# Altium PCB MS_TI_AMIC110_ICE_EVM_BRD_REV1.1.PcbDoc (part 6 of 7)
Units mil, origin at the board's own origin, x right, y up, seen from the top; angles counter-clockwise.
Board outline 3464.57 x 2204.72 mil, 8 copper layers (TopLayer - S1 (.GTL), MidLayer1 - S2 (.G1), MidLayer2 - S3 (.G2), MidLayer3 - S4 (.G3), MidLayer4 - S5 (.G4), MidLayer5 - S6 (.G5), MidLayer6 - S7 (.G6), BottomLayer - S8 (.GBL)), stack 58.937 mil thick; 504 components, 369 nets, 1811 pads, 874 vias.
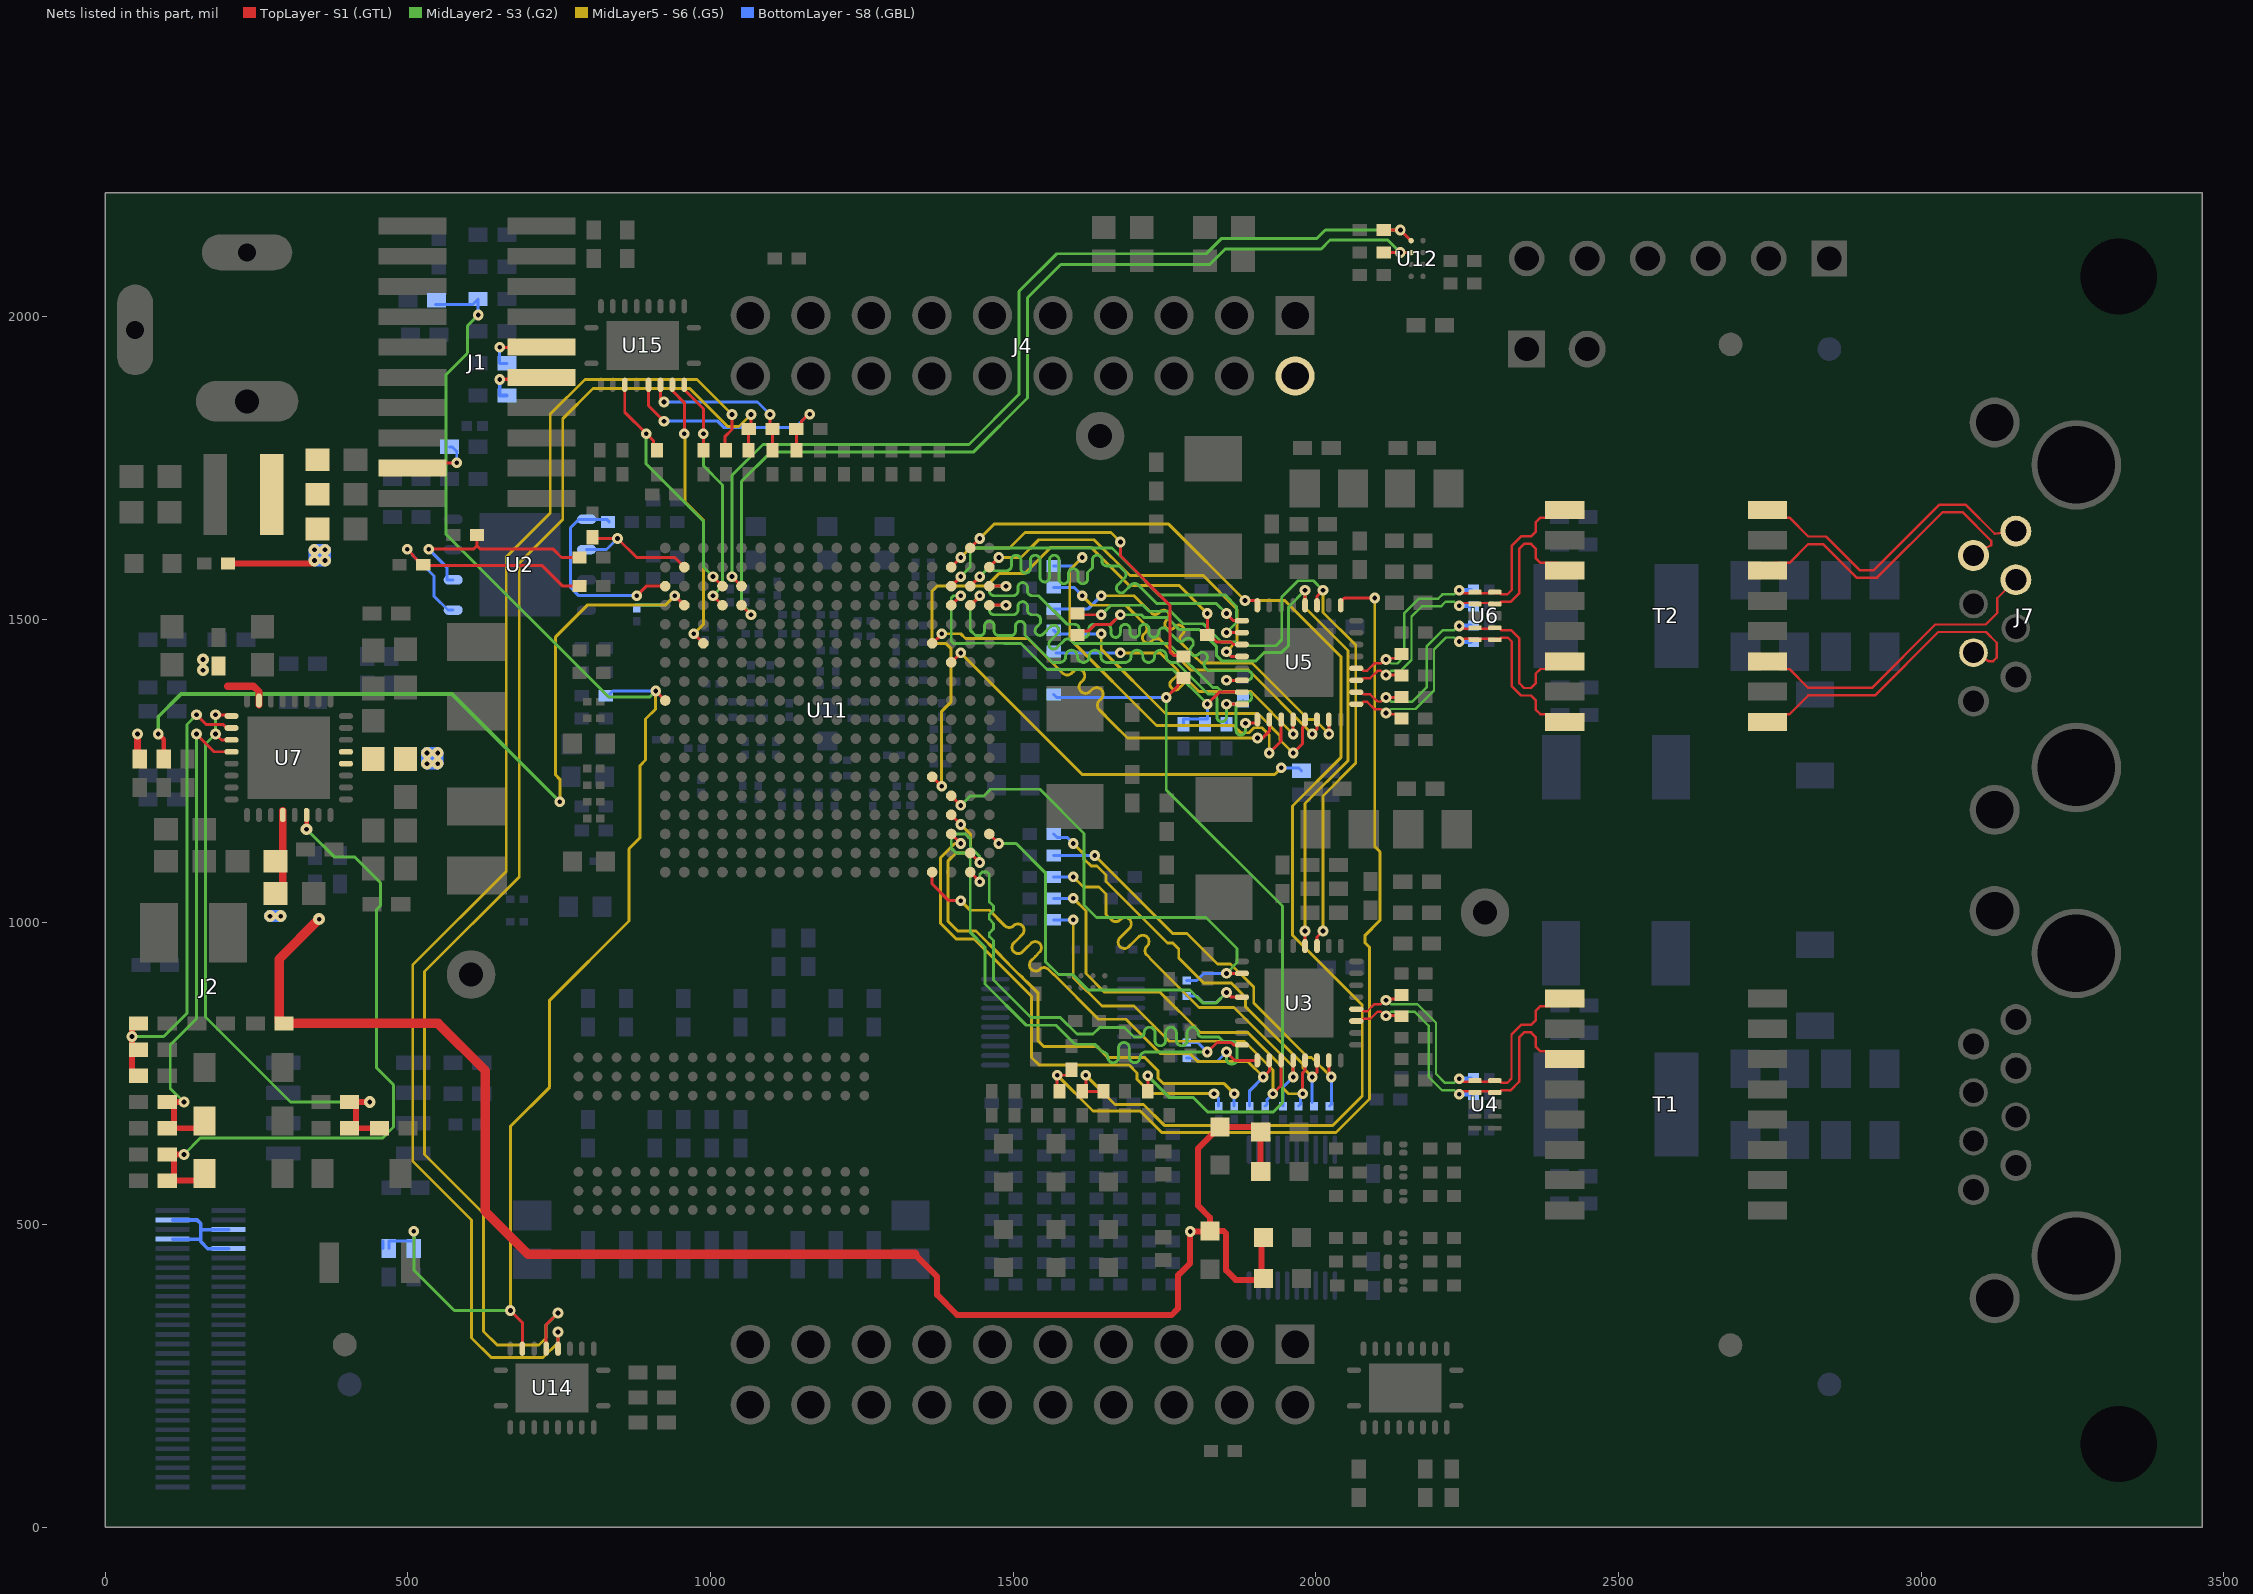
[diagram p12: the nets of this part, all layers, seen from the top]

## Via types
v1: diameter 17.72, hole 7.87, TopLayer - S1 (.GTL) to BottomLayer - S8 (.GBL), 746 vias
v2: diameter 19.68, hole 7.87, TopLayer - S1 (.GTL) to BottomLayer - S8 (.GBL), 128 vias

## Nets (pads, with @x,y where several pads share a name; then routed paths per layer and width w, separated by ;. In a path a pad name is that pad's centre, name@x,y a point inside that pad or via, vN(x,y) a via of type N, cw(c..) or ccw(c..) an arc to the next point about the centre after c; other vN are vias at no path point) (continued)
PHY1_RXD2: R200.2 U3.32 U11.U2 | length 969.8
  TopLayer - S1 (.GTL) w4.92: U11.U2@1429.13,1114.17 v1(1444.88,1098.43) ; v1(1820.87,785.43) 1836.61,801.18 1860.24,801.18 1864.17,797.24 U3.32@1877.95,797.24
  MidLayer2 - S3 (.G2) w4.68: v1(1444.88,1098.43) 1444.88,1108.27 1429.13,1124.02 1429.13,1137.8 1421.26,1145.67 1405.51,1145.67 1397.64,1137.8 1397.64,1122.05 1405.51,1114.17 1420.28,1114.17 1429.13,1105.31 1429.13,983.27 1453.74,958.66 1453.74,897.64 1521.65,829.72 1570.87,829.72 1602.36,798.23 1634.84,798.23 1647.64,785.43 cw(c1647.64,776.57) 1656.5,776.57 ccw(c1665.35,776.57) 1665.35,767.72 ccw(c1665.35,776.57) 1674.21,776.57 1674.21,785.43 1674.21,792.31 cw(c1683.07,792.31) 1683.07,801.17 cw(c1683.07,792.31) 1691.93,792.31 1691.93,785.43 1691.93,776.59 ccw(c1700.79,776.59) 1700.79,767.73 ccw(c1700.79,776.59) 1709.65,776.58 cw(c1718.5,776.57) 1718.5,785.43 1725.39,785.43 v1(1820.87,785.43)
  BottomLayer - S8 (.GBL) w4.92: R200.2@1786.61,801.18 1805.12,801.18 v1(1820.87,785.43)
PHY1_RXD3: R199.2 U3.1 U11.U1 | length 1010.6
  TopLayer - S1 (.GTL) w4.92: U11.U1@1429.13,1082.68 v1(1444.88,1066.93) ; v1@1851.69,785.76 1865.79,771.65 U3.1@1903.54,771.65 U3.1@1903.54,778.54
  MidLayer2 - S3 (.G2) w4.68: v1(1444.88,1066.93) 1444.88,1078.74 1448.82,1082.68 1456.69,1082.68 1460.63,1078.74 1460.63,1033.46 1467.52,1026.57 1467.52,1019.69 1460.63,1012.8 1460.63,1004.92 1467.52,998.03 1467.52,989.17 1460.63,982.28 1460.63,976.38 1467.52,969.49 1467.52,904.53 1529.53,842.52 1577.76,842.52 1605.31,814.96 1631.89,814.96 1643.09,826.16 1683.68,826.16 1699.8,810.04 1707.68,810.04 1709.04,810.04 ccw(c1709.04,817.54) 1716.54,817.54 cw(c1725.39,817.54) 1725.39,826.4 cw(c1725.39,817.54) 1734.25,817.54 1734.25,810.04 1734.25,804.51 ccw(c1743.11,804.51) 1743.11,795.65 ccw(c1743.11,804.51) 1751.97,804.51 1751.97,810.04 1751.97,817.54 cw(c1760.83,817.54) 1760.83,826.4 cw(c1760.83,817.54) 1769.69,817.54 1769.69,810.04 1769.69,804.51 ccw(c1778.54,804.51) 1778.54,795.65 ccw(c1778.54,804.51) 1787.4,804.51 1787.4,810.04 1787.4,817.54 cw(c1796.26,817.54) 1796.26,826.4 cw(c1796.26,817.54) 1805.12,817.54 ccw(c1812.62,817.54) 1812.62,810.04 1813.98,810.04 1839.57,810.04 1846.46,803.15 1862.2,803.15 cw(c1862.2,795.28) 1870.08,795.28 1870.08,773.62 cw(c1862.2,773.62) 1862.2,765.75 1860.24,765.75 cw(c1860.24,773.62) 1852.36,773.62 v1(1852.36,785.43)
  BottomLayer - S8 (.GBL) w4.92: R199.2@1786.61,775.59 1802.17,775.59 1808.07,769.68 1836.61,769.68 v1(1852.36,785.43)
PHY1_RXDV: R205.2 U3.26 U11.T5 | length 813.9
  TopLayer - S1 (.GTL) w4.92: U11.T5@1397.64,1208.66 v1(1413.39,1192.91) ; v1@1851.8,914.43 1852.72,915.35 U3.26@1877.95,915.35
  MidLayer2 - S3 (.G2) w4.68: v1(1413.39,1192.91) 1429.13,1208.66 1451.77,1208.66 1462.6,1219.49 1544.29,1219.49 1617.13,1146.65 1617.13,1028.54 1637.8,1007.87 1818.9,1007.87 1870.08,956.69 1870.08,933.07 v1(1852.36,915.35)
  BottomLayer - S8 (.GBL) w4.92: R205.2@1786.61,903.54 1803.15,903.54 1814.96,915.35 v1(1852.36,915.35)
PHY1_RXER: R204.2 U3.28 U11.V3 | length 706.8
  TopLayer - S1 (.GTL) w4.92: U11.V3@1460.63,1145.67 v1(1476.38,1129.92) ; v1(1852.36,883.86) 1860.24,875.98 U3.28@1877.95,875.98
  MidLayer2 - S3 (.G2) w4.92: v1(1476.38,1129.92) 1504.92,1129.92 1553.15,1081.69 1553.15,935.04 1574.8,913.39 1598.43,913.39 1624.02,887.8 1792.32,887.8 1813.98,866.14 1834.65,866.14 v1(1852.36,883.86)
  BottomLayer - S8 (.GBL) w4.92: R204.2@1786.61,877.95 1803.15,877.95 1813.98,867.13 1835.63,867.13 v1(1852.36,883.86)
PHY1_TD_N: C29.2 R43.1 T1.3 U3.11 U4.2 U4.9 | length 622.6
  TopLayer - S1 (.GTL) w3.98: U3.11@2066.93,836.61 2074.8,836.61 2078.43,840.24 2090.11,840.24 2101.93,852.05 2107.58,852.05 2114.15,845.47 v1(2116.14,845.47) ; v1(2237.2,715.55) 2241.93,720.28 2261.32,720.28 U4.2@2263.09,718.5 2264.86,720.28 2294.19,720.28 U4.9@2295.96,718.5 2303.15,718.5 2306.77,722.13 2321.73,722.13 2335.87,736.26 2335.87,809.49 2344.17,817.8 2355.71,817.8 2363.19,810.32 2363.19,794.29 2371.06,786.42 2398.62,786.42 T1.3@2411.22,773.82
  TopLayer - S1 (.GTL) w4.92: v1(2116.14,845.47) 2140.75,845.47 R43.1@2141.73,844.49
  MidLayer2 - S3 (.G2) w3.98: v1(2116.14,845.47) 2118.11,845.47 2124.78,852.15 2163.02,852.15 2186.42,828.75 2186.42,744.5 2208.69,722.22 2228.56,722.22 2235.24,715.55 v1(2237.2,715.55)
  BottomLayer - S8 (.GBL) w7.87: v1(2237.2,715.55) C29.2@2255.91,715.55
PHY1_TD_P: C28.2 R42.1 T1.1 U3.12 U4.1 U4.10 | length 622.7
  TopLayer - S1 (.GTL) w3.98: U3.12@2066.93,856.3 2074.8,856.3 2078.43,852.68 2084.96,852.68 2096.77,864.49 2107.58,864.49 2114.15,871.06 v1(2116.14,871.06) ; R42.1@2134.84,873.03 R42.1@2141.73,879.92 ; v1(2237.2,741.14) 2241.93,736.42 2261.32,736.42 U4.1@2263.09,738.19 2264.86,736.42 2294.19,736.42 U4.10@2295.96,738.19 2303.15,738.19 2306.77,734.57 2316.58,734.57 2323.43,741.41 2323.43,814.64 2339.02,830.24 2355.71,830.24 2363.19,837.72 2363.19,853.35 2371.06,861.22 2398.62,861.22 T1.1@2411.22,873.82
  TopLayer - S1 (.GTL) w4.92: v1@2118.11,873.03 R42.1@2134.84,873.03
  MidLayer2 - S3 (.G2) w3.98: v1(2116.14,871.06) 2118.11,871.06 2124.78,864.39 2168.09,864.39 2198.66,833.82 2198.66,749.57 2213.76,734.47 2228.56,734.47 2235.24,741.14 v1(2237.2,741.14)
  BottomLayer - S8 (.GBL) w7.87: v1(2237.2,741.14) C28.2@2255.91,741.14
PHY1_TXCLK: R196.2 U3.2 U11.R1 | length 905.6
  TopLayer - S1 (.GTL) w4.92: U11.R1@1366.14,1082.68 1366.14,1062.99 1393.7,1035.43 v1(1413.39,1035.43) ; v1@1913.15,744.18 1923.23,754.26 U3.2@1923.23,771.65
  MidLayer5 - S6 (.G5) w4.68: v1(1413.39,1035.43) 1429.13,1019.68 1460.63,1019.68 1486.22,994.09 ccw(c1493.44,1001.32) 1500.67,994.09 cw(c1507.89,986.87) 1515.12,994.09 cw(c1507.89,986.87) 1515.12,979.65 1507.89,972.42 1501,965.53 ccw(c1508.22,958.3) 1501,951.08 ccw(c1508.22,958.3) 1515.45,951.08 1522.34,957.97 1529.24,964.87 cw(c1536.46,957.64) 1543.69,964.87 cw(c1536.46,957.64) 1543.69,950.42 1536.79,943.52 1529.9,936.63 ccw(c1537.12,929.41) 1529.89,922.18 ccw(c1537.12,929.41) 1544.09,921.94 ccw(c1537.12,929.41) 1544.26,922.1 ; 1544.01,921.85 cw(c1551.24,914.63) 1544.1,921.93 ; 1544.34,922.18 cw(c1537.12,929.41) 1544.26,922.1 ; v1(1913.39,744.09) 1887.6,769.88 1804.92,769.88 1792.32,782.48 1743.31,782.48 1686.22,839.57 1641.16,839.57 1567.34,913.39 1566.93,913.39 1558.46,921.85 ccw(c1551.24,914.63) 1544.27,922.09 ; 1544.1,921.93 cw(c1551.24,914.63) 1544.27,922.09 ; 1544.1,921.93 1544.26,922.1
  BottomLayer - S8 (.GBL) w4.92: R196.2@1890.75,696.06 1890.75,721.46 v1(1913.39,744.09)
PHY1_TXD0: R159.2 R194.2 U3.4 | length 734.8
  TopLayer - S1 (.GTL) w4.92: v1@1962.6,748.03 U3.4@1962.6,771.65
  MidLayer5 - S6 (.G5) w4.68: v1(1599.41,1074.8) 1616.14,1058.07 1641.73,1058.07 1653.54,1046.26 1653.54,1012.8 1662.4,1003.94 ccw(c1669.71,1011.24) 1677.02,1003.94 1677.63,1004.55 cw(c1684.93,997.24) 1692.24,1004.55 cw(c1684.93,997.24) 1692.24,989.93 1684.32,982.01 1676.41,974.1 ccw(c1683.72,966.79) 1676.41,959.48 ccw(c1683.72,966.79) 1691.02,959.48 1698.94,967.4 1706.86,975.31 cw(c1714.16,968.01) 1721.47,975.31 cw(c1714.16,968.01) 1721.47,960.7 1720.86,960.09 ccw(c1728.17,952.78) 1720.86,945.47 1730.31,936.02 1807.09,859.25 1864.96,859.25 1962.6,761.61 v1(1962.6,744.09)
  BottomLayer - S8 (.GBL) w4.92: R159.2@1566.93,1074.8 v1(1599.41,1074.8) ; R194.2@1945.87,696.06 1945.87,727.36 v1(1962.6,744.09)
PHY1_TXD1: R158.2 R193.2 U3.5 | length 705.6
  TopLayer - S1 (.GTL) w4.92: v1(1978.35,716.54) 1978.35,750.98 1982.28,754.92 U3.5@1982.28,771.65
  MidLayer5 - S6 (.G5) w4.68: v1(1599.41,1039.37) 1620.08,1018.7 1620.08,915.35 1650.59,884.84 1742.13,884.84 1809.45,817.52 1887.6,817.52 1944.88,760.24 1944.88,726.38 1954.72,716.54 v1(1978.35,716.54)
  BottomLayer - S8 (.GBL) w4.92: R158.2@1566.93,1039.37 v1(1599.41,1039.37) ; R193.2@1971.46,696.06 1974.41,699.02 1974.41,712.6 v1(1978.35,716.54)
PHY1_TXD2: R157.2 R192.2 U3.6 | length 698.7
  TopLayer - S1 (.GTL) w4.92: v1(1994.09,744.09) 2001.97,751.97 U3.6@2001.97,771.65
  MidLayer5 - S6 (.G5) w4.68: v1(1599.41,1129.92) 1617.13,1112.2 1617.13,1104.33 1628.94,1092.52 1638.78,1092.52 1653.54,1077.76 1653.54,1066.93 1754.92,965.55 1763.78,965.55 1773.62,955.71 1773.62,940.94 1814.96,899.61 1860.24,899.61 1883.86,875.98 1883.86,860.24 1978.84,765.26 1978.84,759.35 v1(1994.09,744.09)
  BottomLayer - S8 (.GBL) w4.92: R157.2@1566.93,1145.67 1572.83,1139.76 1589.57,1139.76 v1(1599.41,1129.92) ; R192.2@1994.09,701.97 v1(1994.09,744.09)
PHY1_TXD3: R156.2 R191.2 U3.7 | length 707.1
  TopLayer - S1 (.GTL) w4.92: U3.7@2021.65,771.65 2021.65,748.03 v1(2025.59,744.09)
  MidLayer5 - S6 (.G5) w4.68: v1@1630.91,1110.24 v1@1632.87,1108.27 ; v1(1634.84,1110.24) 1763.78,981.3 1787.4,981.3 1837.6,931.1 1859.25,931.1 1897.64,892.72 1897.64,866.14 1987.2,776.57 1993.11,776.57 v1(2025.59,744.09)
  BottomLayer - S8 (.GBL) w4.92: R156.2@1566.93,1110.24 v1(1634.84,1110.24) ; R191.2@2022.64,696.06 2025.59,699.02 v1(2025.59,744.09)
PHY1_TXEN: R154.2 R195.2 U3.3 | length 646.4
  TopLayer - S1 (.GTL) w4.92: v1(1929.13,716.54) 1940.88,728.28 ; 1940.92,728.24 1942.91,730.23 U3.3@1942.91,771.65
  MidLayer5 - S6 (.G5) w4.68: v1(1599.41,1003.94) 1599.41,908.82 1646.62,861.61 1699.41,861.61 1757.68,803.35 1881.3,803.35 1929.13,755.51 v1(1929.13,716.54)
  BottomLayer - S8 (.GBL) w4.92: R154.2@1566.93,1003.94 v1(1599.41,1003.94) ; R195.2@1916.34,696.06 1919.29,699.02 1919.29,706.69 v1(1929.13,716.54)
PHY2_COL: R73.1 U11.T17 | length 549.8
  TopLayer - S1 (.GTL) w4.92: U11.T17@1397.64,1586.61 v1(1413.39,1602.36) ; v1(1677.17,1627.95) 1677.17,1605.32 1758.86,1523.62 1758.86,1446.85 1764.76,1440.94 R73.1@1781.5,1440.94
  MidLayer5 - S6 (.G5) w4.68: v1(1413.39,1602.36) 1429.13,1618.11 1494.09,1618.11 1519.69,1643.7 1661.42,1643.7 v1(1677.17,1627.95)
PHY2_CRS: R237.2 U5.27 U11.R6 | length 999.8
  TopLayer - S1 (.GTL) w4.92: U11.R6@1366.14,1240.16 v1(1381.89,1224.41) ; v1(1820.87,1509.84) 1820.87,1478.35 1836.61,1462.6 1860.24,1462.6 1864.17,1458.66 U5.27@1877.95,1458.66
  MidLayer5 - S6 (.G5) w4.92: v1(1381.89,1224.41) 1381.89,1348.43 1397.64,1364.17 1397.64,1451.77 1389.27,1460.14 1374.51,1460.14 1366.14,1468.5 1366.14,1547.24 1374.02,1555.12 1455.71,1555.12 1476.38,1575.79 1518.7,1575.79 1562.01,1619.09 1628.94,1619.09 1691.93,1556.1 1774.61,1556.1 v1(1820.87,1509.84)
PHY2_LED0: R29.2 R189.2 U5.17 | length 1537.7
  TopLayer - S1 (.GTL) w4.92: R29.2@1572.83,720.47 v1@1572.83,745.08 ; v1(1572.83,747.05) 1589.57,747.05 R189.2@1596.46,753.94 ; U5.17@2041.34,1523.62 2041.34,1529.53 2047.24,1535.43 v1(2097.44,1535.43)
  MidLayer5 - S6 (.G5) w4.92: v1(1572.83,747.05) 1631.89,687.99 1710.04,687.99 1745.47,652.56 2033.46,652.56 2088.58,707.68 2088.58,958.66 2081.69,965.55 2081.69,978.35 2106.3,1002.95 2106.3,1116.14 2097.44,1125 v1(2097.44,1535.43)
PHY2_LED1: R30.2 R236.2 U5.24 U11.U18 | length 2128.6
  TopLayer - S1 (.GTL) w4.92: U11.U18@1429.13,1618.11 v1(1444.92,1633.87) ; R236.2@1614.17,720.47 R30.2@1649.61,720.47 R30.2@1651.57,720.47 ; R236.2@1620.08,721.46 v1(1620.08,747.05) ; v1(1882.87,1531.5) 1903.54,1531.5 U5.24@1903.54,1523.62
  MidLayer5 - S6 (.G5) w4.92: v1(1444.92,1633.87) 1468.53,1657.48 1756.89,1657.48 v1(1882.87,1531.5) 1948.82,1531.5 2041.34,1438.98 2041.34,1271.65 1961.61,1191.93 1961.61,978.35 2076.77,863.19 2076.77,712.6 2028.54,664.37 1749.8,664.37 1715.35,698.82 1668.31,698.82 v1(1620.08,747.05)
PHY2_LED2: R31.2 R71.1 R163.1 | length 1275
  TopLayer - S1 (.GTL) w4.92: R31.2@1722.44,720.47 v1(1722.44,746.06) ; v1(1752.95,1371.06) 1772.64,1390.75 1772.64,1404.53 1780.51,1404.53 R71.1@1781.5,1403.54 R71.1@1789.37,1403.54
  MidLayer2 - S3 (.G2) w4.92: v1(1722.44,746.06) 1757.87,710.63 1797.24,710.63 1821.85,686.02 1929.13,686.02 1944.88,701.77 1944.88,1026.57 1752.95,1218.5 v1(1752.95,1371.06)
  BottomLayer - S8 (.GBL) w4.92: R163.1@1566.93,1375.98 1571.85,1371.06 v1(1752.95,1371.06)
PHY2_RD_N: C54.2 R61.1 T2.8 U5.9 U6.5 U6.6 | length 610
  TopLayer - S1 (.GTL) w3.98: U5.9@2066.93,1360.24 2074.8,1360.24 2078.43,1363.86 2084.96,1363.86 2096.77,1352.05 2107.58,1352.05 2114.15,1345.47 v1(2116.14,1345.47) v1@2118.11,1343.5 ; R61.1@2134.84,1343.5 R61.1@2141.73,1336.61 ; v1@2239.19,1463.58 v1(2237.2,1463.58) 2241.93,1468.31 U6.6@2304.92,1468.31 ; U6.6@2305.12,1468.5 2306.77,1470.16 2317.17,1470.16 2324.02,1463.31 2324.02,1389.49 2339.02,1374.49 2355.71,1374.49 2363.19,1367.01 2363.19,1351.38 2371.06,1343.5 2398.62,1343.5 T2.8@2411.22,1330.91
  TopLayer - S1 (.GTL) w4.92: v1@2118.11,1343.5 R61.1@2134.84,1343.5
  MidLayer2 - S3 (.G2) w3.98: v1(2116.14,1345.47) 2118.11,1345.47 2124.78,1352.15 2164.74,1352.15 2195.31,1382.72 2195.31,1450.43 2215.14,1470.26 2228.56,1470.26 2235.24,1463.58 v1(2237.2,1463.58)
  BottomLayer - S8 (.GBL) w7.87: v1(2237.2,1463.58) C54.2@2255.91,1463.58
PHY2_RD_P: C53.2 R60.1 T2.6 U5.10 U6.4 U6.7 | length 604.7
  TopLayer - S1 (.GTL) w3.98: U5.10@2066.93,1379.92 2074.8,1379.92 2078.43,1376.3 2090.11,1376.3 2101.93,1364.49 2107.58,1364.49 2114.15,1371.06 v1(2116.14,1371.06) ; v1(2237.2,1489.17) 2241.93,1484.45 U6.7@2304.92,1484.45 ; U6.7@2305.12,1484.25 2306.77,1482.6 2322.32,1482.6 2336.46,1468.46 2336.46,1394.65 2344.17,1386.93 2355.71,1386.93 2363.19,1394.41 2363.19,1410.43 2371.06,1418.31 2398.62,1418.31 T2.6@2411.22,1430.91
  TopLayer - S1 (.GTL) w4.92: v1(2116.14,1371.06) R60.1@2141.73,1371.06
  MidLayer2 - S3 (.G2) w3.98: v1(2116.14,1371.06) 2118.11,1371.06 2124.78,1364.39 2159.67,1364.39 2183.07,1387.8 2183.07,1455.5 2210.07,1482.5 2228.56,1482.5 2235.24,1489.17 v1(2237.2,1489.17)
  BottomLayer - S8 (.GBL) w7.87: v1(2237.2,1489.17) C53.2@2255.91,1489.17
PHY2_RJ_RD_N: J7.6 T2.9 | length 516.7
  TopLayer - S1 (.GTL) w3.98: T2.9@2746.26,1330.91 2758.86,1343.5 2782.48,1343.5 2813.66,1374.68 2923.9,1374.68 3028.54,1479.33 3107.28,1479.33 3125,1461.61 3125,1437.01 3119.09,1431.1 3112.2,1431.1 J7.6@3086.61,1445.28
PHY2_RJ_RD_P: J7.3 T2.11 | length 516.7
  TopLayer - S1 (.GTL) w3.98: T2.11@2746.26,1430.91 2758.86,1418.31 2782.48,1418.31 2813.66,1387.13 2918.74,1387.13 3023.39,1491.77 3106.93,1491.77 3125.98,1510.83 3125.98,1535.04 J7.3@3156.69,1565.75
PHY2_RJ_TD_N: J7.2 T2.14 | length 516.6
  TopLayer - S1 (.GTL) w3.98: T2.14@2746.26,1580.91 2758.86,1593.5 2782.48,1593.5 2813.66,1624.68 2838.04,1624.68 2893.47,1569.25 2927.52,1569.25 3035.79,1677.52 3068.54,1677.52 3116.14,1629.92 3116.14,1623.03 J7.2@3086.61,1605.91
PHY2_RJ_TD_P: J7.1 T2.16 | length 516.5
  TopLayer - S1 (.GTL) w3.98: T2.16@2746.26,1680.91 2758.86,1668.31 2782.48,1668.31 2813.66,1637.13 2843.19,1637.13 2898.62,1581.69 2922.37,1581.69 3030.63,1689.96 3073.7,1689.96 3121.92,1641.73 ; 3122.05,1641.73 J7.1@3156.69,1646.06
PHY2_RXCLK: U5.25 U11.U16 | length 810.3
  TopLayer - S1 (.GTL) w4.92: U11.U16@1428.24,1554.2 v1(1444.92,1570.88) ; v1(1852.36,1509.84) 1864.17,1498.03 U5.25@1877.95,1498.03
  MidLayer2 - S3 (.G2) w4.68: v1(1444.92,1570.88) 1454.75,1580.71 1489.17,1580.71 ccw(c1489.17,1588.58) 1497.05,1588.58 1497.05,1598.43 cw(c1504.92,1598.43) 1504.92,1606.3 cw(c1504.92,1598.43) 1512.8,1598.46 1512.8,1584.65 ccw(c1520.67,1584.65) 1520.67,1576.77 ccw(c1520.67,1584.65) 1528.54,1584.65 1528.54,1598.43 cw(c1536.42,1598.43) 1536.42,1606.3 cw(c1536.42,1598.43) 1544.29,1598.46 1544.29,1569.88 ccw(c1552.17,1569.88) 1552.17,1562.01 ccw(c1552.17,1569.88) 1560.04,1569.88 1560.04,1598.43 cw(c1567.91,1598.43) 1567.91,1606.3 cw(c1567.91,1598.43) 1575.79,1598.49 1575.79,1566.93 ccw(c1583.66,1566.93) 1583.66,1559.06 ccw(c1583.66,1566.93) 1591.54,1566.93 1591.54,1575.98 cw(c1599.41,1575.98) 1599.41,1583.86 cw(c1599.41,1575.98) 1607.28,1575.98 1607.28,1566.93 ccw(c1615.16,1566.93) 1615.16,1559.06 ccw(c1615.16,1566.93) 1623.03,1566.93 1623.03,1577.76 1630.91,1585.63 1630.91,1598.43 cw(c1638.78,1598.43) 1638.78,1606.3 cw(c1638.78,1598.43) 1646.65,1598.43 1646.65,1596.46 ccw(c1654.53,1596.46) 1654.53,1588.58 1675.2,1588.58 1684.06,1579.72 cw(c1678.49,1574.16) 1684.06,1568.59 1672.96,1557.5 ccw(c1678.56,1551.96) 1672.99,1546.39 ccw(c1678.56,1551.96) 1684.12,1546.38 1695.2,1557.46 cw(c1700.76,1551.89) 1706.33,1557.45 1737.2,1526.57 1835.63,1526.57 v1(1852.36,1509.84)
PHY2_RXD0: U5.30 U11.V16 | length 809.4
  TopLayer - S1 (.GTL) w4.92: U11.V16@1460.63,1555.12 v1@1488.3,1555.12 ; v1(1852.36,1399.61) U5.30@1877.95,1399.61
  MidLayer2 - S3 (.G2) w4.68: v1(1488.19,1555.12) 1468.5,1555.12 ccw(c1468.5,1547.24) 1460.63,1547.24 ccw(c1468.5,1547.24) 1468.5,1539.37 1500,1539.37 ccw(c1500,1547.24) 1507.87,1547.24 1507.87,1553.15 cw(c1515.75,1553.15) 1515.75,1561.02 cw(c1515.75,1553.15) 1523.62,1553.15 1523.62,1547.24 ccw(c1531.5,1547.24) 1531.5,1539.37 1542.13,1539.37 1589.37,1492.13 1601.38,1492.13 cw(c1601.38,1484.25) 1609.25,1484.25 1609.25,1478.35 ccw(c1617.13,1478.35) 1617.13,1470.47 ccw(c1617.13,1478.35) 1625,1478.35 1625,1484.25 cw(c1632.87,1484.25) 1632.87,1492.13 1653.54,1492.13 cw(c1653.54,1484.25) 1661.42,1484.25 1661.42,1478.35 ccw(c1669.29,1478.35) 1669.29,1470.47 ccw(c1669.29,1478.35) 1677.17,1478.35 1677.17,1484.25 cw(c1685.04,1484.25) 1685.04,1492.13 cw(c1685.04,1484.25) 1692.91,1484.25 1692.91,1478.35 ccw(c1700.79,1478.35) 1700.79,1470.47 ccw(c1700.79,1478.35) 1708.66,1478.35 1708.66,1484.25 cw(c1716.54,1484.25) 1716.54,1492.13 cw(c1716.54,1484.25) 1724.41,1484.25 1724.41,1478.35 ccw(c1732.28,1478.35) 1732.28,1470.47 ccw(c1732.28,1478.35) 1740.16,1478.35 cw(c1748.03,1478.35) 1748.03,1486.22 1750.98,1486.22 1771.16,1466.04 ccw(c1776.99,1471.88) 1782.83,1466.04 1783.64,1466.86 cw(c1789.47,1461.02) 1795.3,1466.86 cw(c1789.47,1461.02) 1795.3,1455.19 1794.49,1454.38 ccw(c1800.32,1448.55) 1794.49,1442.71 ccw(c1800.32,1448.55) 1806.15,1442.71 1806.97,1443.53 cw(c1812.8,1437.7) 1818.63,1443.53 cw(c1812.8,1437.7) 1818.63,1431.86 1817.82,1431.05 ccw(c1823.65,1425.22) 1817.82,1419.39 1821.85,1415.35 1822.83,1415.35 1886.81,1415.35 cw(c1886.81,1407.48) 1894.68,1407.48 cw(c1886.81,1407.48) 1886.81,1399.61 v1(1852.36,1399.61)
PHY2_RXD1: R67.1 R72.2 U5.31 U11.T15 | length 715.1
  TopLayer - S1 (.GTL) w4.92: U11.T15@1397.64,1523.62 1401.57,1527.56 1401.71,1527.56 1409.45,1535.29 1409.45,1535.43 v1(1413.39,1539.37) ; v1(1820.87,1360.24) 1840.55,1379.92 U5.31@1877.95,1379.92
  MidLayer2 - S3 (.G2) w4.68: v1(1413.39,1539.37) 1401.57,1539.37 1397.64,1535.43 1397.64,1464.76 1401.77,1460.63 1429.53,1460.63 1429.61,1460.71 1484.96,1460.71 1485.04,1460.63 1512.8,1460.63 1556.1,1417.32 1763.78,1417.32 v1(1820.87,1360.24)
  BottomLayer - S8 (.GBL) w4.92: R72.2@1781.5,1326.77 1781.5,1335.63 1820.87,1335.63 v1(1820.87,1360.24)
PHY2_RXD2: R68.1 R75.2 U5.32 U11.U15 | length 876.8
  TopLayer - S1 (.GTL) w4.92: U11.U15@1429.02,1523.62 1432.96,1527.56 1434.06,1527.56 1440.83,1534.33 1440.83,1535.43 v1@1444.77,1539.37 ; v1(1852.36,1360.24) U5.32@1877.95,1360.24
  MidLayer2 - S3 (.G2) w4.68: v1(1444.92,1539.38) 1429.13,1523.6 1429.13,1482.28 1437.99,1473.43 1444.88,1473.43 ccw(c1444.88,1481.3) 1452.76,1481.3 1452.76,1489.17 cw(c1460.63,1489.17) 1460.63,1497.05 cw(c1460.63,1489.17) 1468.5,1489.17 1468.5,1481.3 ccw(c1476.38,1481.3) 1476.38,1473.43 1496.06,1473.43 ccw(c1496.06,1481.3) 1503.94,1481.3 1503.94,1489.17 cw(c1511.81,1489.17) 1511.81,1497.05 cw(c1511.81,1489.17) 1519.68,1489.17 1519.69,1474.41 1564.96,1429.13 1576.77,1429.13 1576.97,1429.13 ccw(c1576.97,1438.86) 1586.69,1438.86 1586.69,1439.7 cw(c1596.42,1439.7) 1596.42,1449.43 cw(c1596.42,1439.7) 1606.14,1439.7 1606.14,1438.86 ccw(c1615.87,1438.86) 1615.87,1429.13 ccw(c1615.87,1438.86) 1625.59,1438.86 1625.59,1439.7 cw(c1635.31,1439.7) 1635.31,1449.43 cw(c1635.31,1439.7) 1645.04,1439.7 1645.04,1438.86 ccw(c1654.76,1438.86) 1654.76,1429.13 1664.49,1429.13 1674.21,1429.13 1685.04,1429.13 ccw(c1685.04,1438.86) 1694.76,1438.86 1694.76,1439.76 cw(c1704.49,1439.76) 1704.49,1449.48 cw(c1704.49,1439.76) 1714.21,1439.76 1714.21,1438.86 ccw(c1723.94,1438.86) 1723.94,1429.13 ccw(c1723.94,1438.86) 1733.66,1438.86 1733.66,1439.76 cw(c1743.39,1439.76) 1743.39,1449.48 cw(c1743.39,1439.76) 1753.11,1439.76 1753.11,1438.86 ccw(c1762.83,1438.86) 1762.83,1429.13 1765.75,1429.13 1769.69,1429.13 1821.85,1376.97 1828.74,1376.97 cw(c1828.74,1369.09) 1836.61,1369.09 1836.61,1338.98 ccw(c1844.49,1338.98) 1844.49,1331.1 ccw(c1844.49,1338.98) 1852.36,1338.98 v1(1852.36,1360.24)
  BottomLayer - S8 (.GBL) w4.92: R68.1@1852.36,1326.77 v1(1852.36,1360.24) 1879.92,1360.24 R75.2@1879.92,1366.14
PHY2_RXD3: U5.1 U11.V15 | length 821.3
  TopLayer - S1 (.GTL) w4.92: U11.V15@1460.63,1523.62 v1(1488.19,1523.62) ; v1(1883.86,1328.74) 1903.54,1328.74 U5.1@1903.54,1334.65
  MidLayer2 - S3 (.G2) w4.68: v1(1488.19,1523.62) 1468.5,1523.62 ccw(c1468.5,1515.75) 1460.63,1515.75 ccw(c1468.5,1515.75) 1468.5,1507.87 1500,1507.87 ccw(c1500,1515.75) 1507.87,1515.75 1507.87,1521.65 cw(c1515.75,1521.65) 1515.75,1529.53 cw(c1515.75,1521.65) 1523.62,1521.65 1523.62,1515.75 ccw(c1531.5,1515.75) 1531.5,1507.87 1537.4,1507.87 cw(c1537.4,1500) 1545.28,1500 1545.28,1494.04 ; 1549.64,1476.13 cw(c1544.08,1481.71) 1538.51,1476.14 cw(c1544.08,1481.71) 1538.51,1487.27 ; 1549.65,1476.14 1561.7,1488.19 cw(c1567.27,1482.62) 1572.83,1488.19 ; 1573.2,1487.82 cw(c1567.63,1482.25) 1573.2,1476.69 1561.15,1464.64 ccw(c1566.72,1459.07) 1561.15,1453.5 ccw(c1566.72,1459.07) 1572.28,1453.49 1584.34,1465.55 ; 1584.35,1465.56 cw(c1589.9,1459.98) 1595.47,1465.55 1600.39,1460.63 1756.89,1460.63 1829.72,1387.8 1837.6,1387.8 1845.47,1379.92 1886.42,1379.92 cw(c1886.42,1372.05) 1894.29,1372.05 cw(c1886.42,1372.05) 1886.42,1364.17 1875.98,1364.17 ccw(c1875.98,1356.3) 1868.11,1356.3 1868.11,1316.93 ccw(c1875.98,1316.93) 1875.98,1309.06 ccw(c1875.98,1316.93) 1883.86,1316.93 v1(1883.86,1328.74) ; 1538.51,1487.27 1545.28,1494.04 ; 1538.51,1487.27 1545.28,1494.04
PHY2_RXDV: U5.26 U11.T16 | length 627.2
  TopLayer - S1 (.GTL) w4.92: U11.T16@1397.64,1555.12 v1(1413.39,1570.87) ; v1(1852.36,1478.35) U5.26@1877.95,1478.35
  MidLayer2 - S3 (.G2) w4.68: v1(1413.39,1570.87) 1429.13,1586.61 1429.13,1610.24 1437.01,1618.11 1663.39,1618.11 1741.14,1540.35 1850.39,1540.35 1869.09,1521.65 1869.09,1495.08 v1(1852.36,1478.35)
PHY2_RXER: U5.28 U11.V17 | length 578.7
  TopLayer - S1 (.GTL) w4.92: U11.V17@1463.6,1589.08 1463.6,1589.56 v1(1476.41,1602.37) v1@1476.41,1601.89 ; v1(1852.36,1446.85) 1860.24,1438.98 U5.28@1877.95,1438.98
  MidLayer5 - S6 (.G5) w4.68: v1(1476.41,1602.37) 1512.8,1602.37 1542.32,1631.89 1633.86,1631.89 1692.91,1572.83 1813.98,1572.83 1870.08,1516.73 1870.08,1464.57 v1(1852.36,1446.85)
PHY2_TD_N: C52.2 R59.1 T2.3 U5.11 U6.2 U6.9 | length 604.9
  TopLayer - S1 (.GTL) w3.98: U5.11@2066.93,1399.61 2074.8,1399.61 2078.43,1403.23 2090.11,1403.23 2101.93,1415.04 2107.58,1415.04 2114.15,1408.46 v1(2116.14,1408.46) ; v1(2237.2,1522.64) 2241.93,1527.36 U6.9@2304.92,1527.36 ; U6.9@2305.12,1527.56 2306.77,1529.21 2321.73,1529.21 2336.46,1543.94 2336.46,1617.17 2344.17,1624.88 2355.71,1624.88 2363.19,1617.4 2363.19,1601.38 2371.06,1593.5 2398.62,1593.5 T2.3@2411.22,1580.91
  TopLayer - S1 (.GTL) w4.92: v1(2116.14,1408.46) R59.1@2141.73,1408.46
  MidLayer2 - S3 (.G2) w3.98: v1(2116.14,1408.46) 2118.11,1408.46 2124.78,1415.14 2139.94,1415.14 2158.11,1433.31 2158.11,1504.76 2175.39,1522.05 2207.09,1522.05 2208.66,1523.62 2214.35,1529.31 2228.56,1529.31 2235.24,1522.64 v1(2237.2,1522.64)
  BottomLayer - S8 (.GBL) w7.87: v1(2237.2,1522.64) C52.2@2255.91,1522.64
PHY2_TD_P: C51.2 R58.1 T2.1 U5.12 U6.1 U6.10 | length 608.2
  TopLayer - S1 (.GTL) w3.98: U5.12@2066.93,1419.29 2074.8,1419.29 2078.43,1415.67 2084.96,1415.67 2096.77,1427.48 2107.58,1427.48 2114.15,1434.05 v1(2116.14,1434.06) v1@2118.11,1436.02 ; R58.1@2134.84,1436.02 R58.1@2141.73,1442.91 ; v1(2237.2,1548.23) 2241.93,1543.5 U6.10@2304.92,1543.5 ; U6.10@2305.12,1543.31 2306.77,1541.65 2316.58,1541.65 2324.02,1549.09 2324.02,1622.32 2339.02,1637.32 2355.71,1637.32 2363.19,1644.8 2363.19,1660.43 2371.06,1668.31 2398.62,1668.31 T2.1@2411.22,1680.91
  TopLayer - S1 (.GTL) w4.92: v1@2118.11,1436.02 R58.1@2134.84,1436.02
  MidLayer2 - S3 (.G2) w3.98: v1(2116.14,1434.06) 2118.11,1434.06 2124.78,1427.38 2134.87,1427.38 2145.87,1438.38 2145.87,1509.84 2168.31,1532.28 2170.32,1534.29 2202.01,1534.29 2209.28,1541.56 2228.56,1541.56 2235.24,1548.23 v1(2237.2,1548.23)
  BottomLayer - S8 (.GBL) w7.87: v1(2237.2,1548.23) C51.2@2255.91,1548.23
PHY2_TXCLK: U5.2 U11.R13 | length 725.9
  TopLayer - S1 (.GTL) w4.92: U11.R13@1366.4,1460.36 1381.89,1475.85 v1(1381.89,1476.38) ; v1@1903.58,1303.85 1911.48,1303.85 1923.23,1315.6 U5.2@1923.23,1334.65
  MidLayer5 - S6 (.G5) w4.68: v1(1381.89,1476.38) 1413.39,1476.38 1421.26,1468.5 1524.61,1468.5 1581.69,1411.42 ccw(c1589.27,1418.99) 1596.84,1411.42 1600.03,1414.61 cw(c1607.6,1407.03) 1615.17,1414.61 cw(c1607.6,1407.03) 1615.17,1399.46 1611.98,1396.27 ccw(c1619.55,1388.7) 1611.98,1381.13 ccw(c1619.55,1388.7) 1627.13,1381.13 1630.32,1384.32 cw(c1637.89,1376.75) 1645.46,1384.32 cw(c1637.89,1376.75) 1645.46,1369.17 1642.27,1365.98 ccw(c1649.84,1358.41) 1642.27,1350.84 1664.37,1328.74 1688.98,1304.13 v1(1903.54,1304.13)
PHY2_TXD0: R167.2 U5.4 | length 514
  TopLayer - S1 (.GTL) w4.92: v1(1962.6,1311.02) U5.4@1962.6,1334.65
  MidLayer5 - S6 (.G5) w4.68: v1(1677.17,1444.88) 1743.11,1444.88 1756.89,1431.1 1763.07,1424.92 1770.49,1417.51 cw(c1765.54,1412.56) 1770.49,1407.62 1760.87,1398 ccw(c1765.81,1393.06) 1760.87,1388.11 1763.34,1385.64 ccw(c1768.28,1390.58) 1773.23,1385.64 1782.85,1395.26 cw(c1787.79,1390.31) 1792.73,1395.26 1805.12,1382.87 1807.09,1380.91 1892.72,1380.91 v1(1962.6,1311.02)
  BottomLayer - S8 (.GBL) w4.92: R167.2@1570.87,1444.88 v1(1677.17,1444.88)
PHY2_TXD1: R166.2 U5.5 | length 562
  TopLayer - S1 (.GTL) w4.92: v1(1962.6,1279.53) 1978.35,1295.28 1978.35,1321.85 1982.28,1325.79 U5.5@1982.28,1334.65
  MidLayer5 - S6 (.G5) w4.68: v1(1645.67,1476.38) 1645.67,1450.79 1751.97,1344.49 1904.53,1344.49 1940.94,1308.07 1940.94,1301.18 v1(1962.6,1279.53)
  BottomLayer - S8 (.GBL) w4.92: R166.2@1566.93,1482.28 1572.83,1476.38 v1(1645.67,1476.38)
PHY2_TXD2: R165.2 U5.6 | length 581.3
  TopLayer - S1 (.GTL) w4.92: v1(1994.09,1311.02) 2001.97,1318.9 U5.6@2001.97,1334.65
  MidLayer5 - S6 (.G5) w4.68: v1(1614.17,1539.37) 1629.92,1523.62 1686.02,1523.62 1718.56,1491.08 cw(c1712.38,1484.9) 1718.56,1478.72 1716.08,1476.25 ccw(c1722.26,1470.07) 1716.08,1463.88 ccw(c1722.26,1470.07) 1728.44,1463.88 1730.92,1466.36 cw(c1737.1,1460.18) 1743.27,1466.37 1793.31,1416.34 1888.78,1416.34 v1(1994.09,1311.02)
  BottomLayer - S8 (.GBL) w4.92: R165.2@1566.93,1553.15 1600.39,1553.15 v1(1614.17,1539.37)
PHY2_TXD3: R164.2 U5.7 | length 633.8
  TopLayer - S1 (.GTL) w4.92: v1(2021.65,1311.02) U5.7@2021.65,1334.65
  MidLayer5 - S6 (.G5) w4.68: v1(1645.67,1539.37) 1699.8,1539.37 1728.35,1510.83 ccw(c1734.53,1517.01) 1740.71,1510.83 1742.82,1512.94 cw(c1749,1506.76) 1755.18,1512.94 cw(c1749,1506.76) 1755.18,1500.58 1753.07,1498.47 ccw(c1759.25,1492.29) 1753.07,1486.11 ccw(c1759.25,1492.29) 1765.43,1486.11 1767.54,1488.22 cw(c1773.72,1482.04) 1779.9,1488.22 cw(c1773.72,1482.04) 1779.9,1475.86 1777.79,1473.75 ccw(c1783.97,1467.57) 1777.79,1461.39 1792.81,1446.36 1798.23,1440.94 1811.02,1428.15 1894.69,1428.15 1988.19,1334.65 1998.03,1334.65 v1(2021.65,1311.02)
  BottomLayer - S8 (.GBL) w4.92: R164.2@1566.93,1517.72 1624.02,1517.72 v1(1645.67,1539.37)
PHY2_TXEN: R160.2 U5.3 | length 690.9
  TopLayer - S1 (.GTL) w4.92: v1(1923.23,1279.53) 1942.91,1299.21 U5.3@1942.91,1334.65
  MidLayer5 - S6 (.G5) w4.68: v1(1614.17,1602.36) 1593.5,1581.69 1593.5,1468.31 1737.01,1324.8 1864.17,1324.8 1875.98,1312.99 1889.76,1312.99 1898.03,1321.26 1911.02,1321.26 1923.23,1309.06 v1(1923.23,1279.53)
  BottomLayer - S8 (.GBL) w4.92: R160.2@1566.93,1588.58 1600.39,1588.58 v1(1614.17,1602.36)
PHY2_WOL: R65.2 U11.T12 | length 675
  TopLayer - S1 (.GTL) w4.92: U11.T12@1397.64,1429.13 v1(1413.39,1444.88)
  MidLayer5 - S6 (.G5) w4.92: v1(1413.39,1444.88) 1614.17,1244.09 1932.09,1244.09 v1(1942.91,1254.92)
  BottomLayer - S8 (.GBL) w4.92: v1(1942.91,1254.92) 1971.46,1254.92 R65.2@1976.38,1250
PHY_MDC: R150.1 U3.20 U5.20 | length 1191.2
  TopLayer - S1 (.GTL) w4.92: R150.1@1606.3,1474.41 1606.3,1481.3 1625,1481.3 1635.83,1492.13 1661.42,1492.13 v1(1677.17,1507.87) ; U3.20@1982.28,960.63 v1(1982.28,985.24) ; U5.20@1982.28,1523.62 v1(1982.28,1548.23)
  MidLayer2 - S3 (.G2) w4.92: v1(1677.17,1507.87) 1711.61,1507.87 1716.54,1502.95 1754.92,1502.95 1774.61,1483.27 1808.07,1483.27 1835.63,1455.71 1835.63,1440.94 1845.47,1431.1 1900.59,1431.1 1915.35,1445.87 1943.9,1445.87 1954.72,1456.69 1954.72,1520.67 v1(1982.28,1548.23)
  MidLayer5 - S6 (.G5) w4.68: v1(1982.28,985.24) 1982.28,1195.87 2053.15,1266.73 2053.15,1448.82 1982.28,1519.68 v1(1982.28,1548.23)
PHY_MDIO: R153.1 U3.19 U5.19 | length 1199.4
  TopLayer - S1 (.GTL) w4.92: R153.1@1606.3,1509.84 1606.3,1507.87 v1(1645.67,1507.87) ; U3.19@2001.97,960.63 2001.97,975.39 v1(2011.81,985.24) ; U5.19@2001.97,1523.62 2001.97,1538.39 v1(2011.81,1548.23)
  MidLayer2 - S3 (.G2) w4.68: v1(1645.67,1507.87) 1661.42,1523.62 1714.57,1523.62 1724.41,1513.78 1759.84,1513.78 1780.51,1493.11 1813.98,1493.11 1844.49,1462.6 1867.13,1462.6 1873.03,1456.69 1934.06,1456.69 1943.9,1466.54 1943.9,1537.4 1970.47,1563.98 1996.06,1563.98 v1(2011.81,1548.23)
  MidLayer5 - S6 (.G5) w4.68: v1(2011.81,985.24) 2011.81,1208.66 2065.94,1262.8 2065.94,1457.68 2011.81,1511.81 v1(2011.81,1548.23)
PMIC_PWRFAIL_SNS: C85.1 D14.2 R95.1 U7.30 | length 1084.9
  TopLayer - S1 (.GTL) w4.92: U7.30@332.97,1169.59 U7.30@332.97,1177.46
  TopLayer - S1 (.GTL) w7.87: v2@332.97,1153.84 U7.30@332.97,1169.59
  TopLayer - S1 (.GTL) w9.84: v1(129.92,616.14) 113.19,616.14 113.19,572.83 163.88,572.83 D14.2@163.88,584.65
  MidLayer2 - S3 (.G2) w4.92: v1(129.92,616.14) 157.48,643.7 458.66,643.7 476.38,661.42 476.38,731.3 447.83,759.84 447.83,1020.23 454.72,1027.12 454.72,1064.96 412.4,1107.28 378.94,1107.28 337.2,1149.02 v2@337.2,1151.98
  other v2: 332.68,1153.54
PMIC_RESETOUTN: C169.2 R102.2 U11.B15 | length 1420.4
  TopLayer - S1 (.GTL) w4.92: v1(940.94,1539.36) U11.B15@956.69,1523.62
  TopLayer - S1 (.GTL) w7.87: v1(87.6,1311.02) 96.46,1302.17 R102.2@96.46,1269.69
  MidLayer2 - S3 (.G2) w5.91: v1(87.6,1311.02) 87.6,1339.57 125,1376.97 572.83,1376.97 v1(750.98,1198.82)
  MidLayer5 - S6 (.G5) w4.92: v1(750.98,1198.82) 750.98,1236.22 744.09,1243.11 744.09,1471.46 796.26,1523.62 925.2,1523.62 v1(940.94,1539.36)
  BottomLayer - S8 (.GBL) w4.92: C169.2@875.98,1523.62 925.2,1523.62 v1(940.94,1539.36)
PMIC_V1V1EN: C83.1 D13.2 R91.1 U7.20 | length 828.4
  TopLayer - S1 (.GTL) w4.92: v1@150.24,1311.05 179.77,1281.53 U7.20@208.32,1281.53
  TopLayer - S1 (.GTL) w9.84: v1(129.92,702.76) 113.19,702.76 113.19,659.45 163.88,659.45 D13.2@163.88,671.26
  MidLayer2 - S3 (.G2) w4.92: v1@129.97,702.7 107.33,725.34 107.33,797.19 150.64,840.5 v1(150.59,1311.02)
PMIC_V1V8EN: C77.1 R84.2 R85.2 U7.17 U7.19 | length 1010.2
  TopLayer - S1 (.GTL) w4.92: v1(182.09,1342.52) 206.69,1342.52 U7.17@208.66,1340.55 ; v1@182.17,1310.9 192.01,1301.05 U7.19@208.75,1301.05
  TopLayer - S1 (.GTL) w9.84: C77.1@403.54,702.76 C77.1@414.37,702.76 ; v2(437.01,702.76) C77.1@414.37,702.76 ; R84.2@452.76,659.45 414.37,659.45 C77.1@414.37,702.76
  MidLayer2 - S3 (.G2) w4.92: v1(182.09,1342.52) v1@182.85,1341.75 ; v1(182.09,1342.52) v1(182.09,1311.02) 165.4,1294.24 165.4,843.45 306.15,702.7 v2@437.05,702.7
PMIC_V3V3EN: C79.1 R87.1 R88.2 U7.18 | length 781.4
  TopLayer - S1 (.GTL) w4.92: v1(150.59,1342.52) 166.23,1326.88 194.49,1326.88 200.51,1320.86 U7.18@208.66,1320.87
  TopLayer - S1 (.GTL) w9.84: R88.2@55.12,746.06 44.29,746.06 v1(44.29,811.02) 44.29,832.68 R87.1@55.12,832.68
  MidLayer2 - S3 (.G2) w4.92: v1(44.29,811.02) 96.5,810.97 134.89,849.36 134.89,1326.72 v1(150.59,1342.52)
RTCK: J1.9 R4.2 | length 95.5
  TopLayer - S1 (.GTL) w5.91: v1(651.57,1896.65) J1.9@708.66,1896.65
  BottomLayer - S8 (.GBL) w5.91: v1(651.57,1896.65) 651.57,1870.08 R4.2@663.39,1870.08
SPI0_CS0N: R217.1 U2.1 U11.A16 | length 338.6
  TopLayer - S1 (.GTL) w4.92: v1(877.95,1539.37) 893.7,1555.12 U11.A16@925.2,1555.12
  BottomLayer - S8 (.GBL) w4.92: R217.1@832.68,1661.42 828.54,1665.55 U2.1@795.28,1665.55 782.68,1665.55 768.7,1651.57 768.7,1553.15 782.48,1539.37 v1(877.95,1539.37)
SPI0_D0: R239.1 U2.2 U11.B17 | length 227.9
  TopLayer - S1 (.GTL) w4.92: R239.1@807.09,1633.86 v1(846.46,1633.86) 877.95,1602.36 940.94,1602.36 U11.B17@956.69,1586.61
  BottomLayer - S8 (.GBL) w4.92: U2.2@795.28,1615.55 828.15,1615.55 v1(846.46,1633.86)
SPI0_D1: R152.1 R238.1 U2.5 | length 448.5
  TopLayer - S1 (.GTL) w4.92: v1(499.02,1616.14) 508.37,1606.79 508.37,1605.34 523.64,1590.06 525.1,1590.06 526.13,1589.03 721.99,1589.03 755.91,1555.12 R152.1@783.46,1555.12
  BottomLayer - S8 (.GBL) w4.92: v1(499.02,1616.14) 508.37,1606.79 508.37,1605.34 523.64,1590.06 525.1,1590.06 543.31,1571.85 543.31,1538.39 566.14,1515.55 U2.5@574.8,1515.55
SPI0_SCLK: R149.1 R240.1 U2.6 | length 352.3
  TopLayer - S1 (.GTL) w4.92: v1(534.45,1616.14) 608.33,1616.14 614.17,1621.98 ; 613.48,1620.37 ccw(c611.8,1622.05) 614.17,1621.98 ; R240.1@614.17,1639.76 614.17,1622.05 ; R149.1@783.46,1602.36 753.94,1602.36 740.16,1616.14 620.08,1616.14 614.17,1622.05 ; 614.17,1621.99 ccw(c611.8,1622.05) 614.17,1622.05 ; 614.17,1621.99 614.17,1622.05
  BottomLayer - S8 (.GBL) w4.92: v1(534.45,1616.14) 564.96,1585.63 564.96,1565.55 U2.6@574.8,1565.55
SPI_D0: R144.2 U14.5 | length 2286
  TopLayer - S1 (.GTL) w4.92: U14.5@748.03,295.28 v1(748.03,322.83) ; R144.2@1023.62,1779.53 1023.62,1802.17 1035.43,1813.98 v1(1035.43,1838.58)
  MidLayer5 - S6 (.G5) w4.68: v1(748.03,322.83) 748.03,305.12 723.43,280.51 637.8,280.51 605.31,312.99 605.31,507.87 507.87,605.32 507.87,929.13 662.4,1083.66 662.4,1603.35 735.24,1676.18 735.24,1839.57 792.32,1896.65 977.36,1896.65 v1(1035.43,1838.58) v1@1036.42,1839.57
SPI_D1_MCASP1_AFSX_MFSRB: R13.1 R147.2 U14.6 | length 2303.9
  TopLayer - S1 (.GTL) w4.92: U14.6@728.35,295.28 728.35,334.65 v1(748.03,354.33) ; R147.2@1062.99,1779.53 R13.1@1062.99,1814.96 1066.93,1818.9 v1(1066.93,1838.58)
  MidLayer5 - S6 (.G5) w4.68: v1(748.03,354.33) 728.35,334.65 728.35,312.99 716.54,301.18 647.64,301.18 625,323.82 625,518.7 527.56,616.14 527.56,918.31 684.06,1074.8 684.06,1593.5 755.91,1665.35 755.91,1831.69 806.1,1881.89 965.55,1881.89 1028.54,1818.9 1047.24,1818.9 v1(1066.93,1838.58)
SPICLK: R12.2 R145.2 U15.6 | length 395.4
  TopLayer - S1 (.GTL) w4.92: 897.64,1853.35 v1(923.23,1827.76) ; U15.6@897.64,1887.8 897.64,1853.45 898.14,1852.94 ; R145.2@1141.73,1779.53 1141.73,1807.09 1150.59,1815.94 1150.59,1828.13 1161.52,1839.06 v1(1163.77,1839.06)
  BottomLayer - S8 (.GBL) w4.92: v1(923.23,1827.76) 1011.81,1827.76 1022.64,1816.93 1139.76,1816.93 1161.9,1839.06 v1(1163.77,1839.06)
SPICS: R13.2 R151.2 U15.7 | length 275.5
  TopLayer - S1 (.GTL) w4.92: U15.7@917.32,1887.8 917.32,1865.35 v1@923.42,1859.25 ; v1(1098.43,1838.58) 1098.43,1818.9 R13.2@1102.36,1814.96 R151.2@1102.36,1779.53
  BottomLayer - S8 (.GBL) w4.92: v1(923.23,1859.25) 1077.76,1859.25 v1(1098.43,1838.58)
SYS_BOOT6_GPIO: R197.2 U11.T3 | length 831.3
  TopLayer - S1 (.GTL) w4.92: U11.T3@1397.64,1145.67 v1(1413.39,1129.92)
  MidLayer5 - S6 (.G5) w4.92: v1(1413.39,1129.92) 1403.54,1129.92 1379.92,1106.3 1379.92,998.03 1405.51,972.44 1435.43,972.44 1530.51,877.36 1530.51,776.18 1542.91,763.78 1691.73,763.78 1704.72,750.79 1704.72,740.35 1728.54,716.54 v1(1831.69,716.54)
  BottomLayer - S8 (.GBL) w4.92: v1(1831.69,716.54) 1839.57,708.66 R197.2@1839.57,696.06
SYS_BOOT7_GPIO: R198.2 U11.T4 | length 881
  TopLayer - S1 (.GTL) w4.92: U11.T4@1397.64,1177.17 v1(1413.39,1161.42)
  MidLayer5 - S6 (.G5) w4.92: v1(1413.39,1161.42) 1429.13,1145.67 1429.13,1119.09 1424.21,1114.17 1405.51,1114.17 1392.72,1101.38 1392.72,1000.98 1408.46,985.24 1438.42,985.24 1480.17,943.49 1480.17,943.41 1486.75,936.83 ; 1486.89,936.97 1486.75,936.83 ; 1514.7,908.88 1522.23,901.35 1522.52,901.35 1541.34,882.53 1541.34,803.74 1550.2,794.88 1638.19,794.88 1656.5,776.57 1716.93,776.57 1739.57,753.94 1739.57,741.73 1748.23,733.07 1848.62,733.07 v1(1865.16,716.54) ; 1515.65,907.93 1509.06,914.52 1508.94,914.52 1493.33,930.12 1493.33,930.25 1486.75,936.83
  BottomLayer - S8 (.GBL) w4.92: R198.2@1865.16,696.06 v1(1865.16,716.54)
SYS_RESETN: C2.2 C3.1 R9.1 R10.1 R138.1 U11.A10 U14.8 | length 2577.5
  TopLayer - S1 (.GTL) w4.92: v1(669.29,358.27) 688.98,338.58 U14.8@688.98,295.28 ; v1(909.45,1381.89) U11.A10@925.2,1366.14
  MidLayer2 - S3 (.G2) w4.92: v1(509.84,489.17) 509.84,425.2 576.77,358.27 v1(669.29,358.27) ; v1(616.14,2002.95) 598.43,1985.24 598.43,1939.96 562.99,1904.53 562.99,1640.75 831.69,1372.05 899.61,1372.05 v1(909.45,1381.89)
  MidLayer5 - S6 (.G5) w4.92: v1(669.29,358.27) 669.29,662.4 734.25,727.36 734.25,871.06 865.16,1001.97 865.16,1121.06 883.86,1139.76 883.86,1258.86 892.72,1267.72 892.72,1335.63 909.45,1352.36 v1(909.45,1381.89)
  BottomLayer - S8 (.GBL) w4.92: C3.1@458.66,460.63 C3.1@458.66,473.43 ; C3.1@468.5,460.63 468.5,473.43 509.84,473.43 v1(509.84,489.17) ; C2.2@545.28,2020.67 607.28,2020.67 R9.1@616.14,2029.53 ; v1(616.14,2002.95) R9.1@616.14,2027.56 ; R138.1@830.71,1374.02 838.58,1381.89 v1(909.45,1381.89)
TCK: J1.11 R5.2 | length 95.5
  TopLayer - S1 (.GTL) w4.92: v1(651.57,1949.8) J1.11@708.66,1949.8
  BottomLayer - S8 (.GBL) w4.92: v1(651.57,1949.8) 651.57,1923.23 R5.2@663.39,1923.23
TDIS: J1.4 R1.2 | length 110.4
  TopLayer - S1 (.GTL) w4.92: J1.4@507.68,1750.2 516.34,1758.86 v1(580.71,1758.86)
  BottomLayer - S8 (.GBL) w4.92: R1.2@568.9,1785.43 572.83,1785.43 580.71,1777.56 v1(580.71,1758.86)
UART0_RX: R55.1 U11.E15 U12.C2 | length 1653.7
  TopLayer - S1 (.GTL) w4.92: U11.E15@1051.18,1523.62 v1(1066.94,1507.87) ; R55.1@2112.2,2106.3 v1(2139.76,2106.3) U12.C2@2157.48,2106.3
  MidLayer2 - S3 (.G2) w4.92: v1(1066.94,1507.87) 1066.94,1510.64 1051.18,1526.39 1051.18,1728.35 1099.41,1776.57 1434.06,1776.57 1523.62,1866.14 1523.62,2031.5 1578.74,2086.61 1824.8,2086.61 1850.39,2112.2 2008.86,2112.2 2023.62,2126.97 2119.09,2126.97 v1(2139.76,2106.3)
UART0_TX: R76.2 U11.E16 U12.D2 | length 1614.3
  TopLayer - S1 (.GTL) w4.92: v1(1035.43,1570.87) U11.E16@1051.18,1555.12 ; R76.2@2112.2,2143.7 v1(2139.76,2143.7) U12.D2@2157.48,2125.98
  MidLayer2 - S3 (.G2) w4.92: v1(1035.43,1570.87) 1035.43,1738.18 1086.61,1789.37 1427.17,1789.37 1509.84,1872.05 1509.84,2042.32 1571.85,2104.33 1818.9,2104.33 1844.49,2129.92 2001.97,2129.92 2015.75,2143.7 v1(2139.76,2143.7)
UART1_DE: U11.C13 U15.8 | length 461.4
  TopLayer - S1 (.GTL) w4.92: U15.8@937.01,1887.8 937.01,1877.95 956.69,1858.27 v1(956.69,1807.09) ; v1(972.44,1476.38) U11.C13@988.19,1460.63
  MidLayer5 - S6 (.G5) w4.72: v1(956.69,1807.09) 957.68,1806.1 957.68,1694.88 988.19,1664.37 988.19,1492.13 v1(972.44,1476.38)
UART1_RX: R215.1 U11.D16 U15.4 | length 434.4
  TopLayer - S1 (.GTL) w4.72: U15.4@858.27,1887.8 858.27,1842.52 v1(893.7,1807.09) 905.51,1795.28 905.51,1785.43 R215.1@911.42,1779.53
  TopLayer - S1 (.GTL) w4.92: v1(1003.94,1570.87) U11.D16@1019.68,1555.12
  MidLayer2 - S3 (.G2) w4.92: v1(893.7,1807.09) 893.7,1756.89 988.19,1662.4 988.19,1586.61 v1(1003.94,1570.87)
UART1_TX: R216.2 U11.D15 U15.9 | length 430.9
  TopLayer - S1 (.GTL) w4.92: U15.9@956.69,1887.8 956.69,1879.92 988.19,1848.43 v1(988.19,1807.09) R216.2@988.19,1779.53 ; v1(1003.94,1539.37) U11.D15@1019.68,1523.62
  MidLayer2 - S3 (.G2) w4.72: v1(988.19,1807.09) 988.19,1753.94 1019.69,1722.44 1019.69,1555.12 v1(1003.94,1539.37)
VCC_3V3_CONTROLCARD_NC: J2.51 J2.54 J2.55 J2.58 | length 221.9
  BottomLayer - S8 (.GBL) w5.91: J2.54@111.22,476.38 157.48,476.38 ; J2.58@111.22,507.87 151.57,507.87 157.48,501.97 157.48,492.13 ; J2.51@203.74,460.63 169.29,460.63 157.48,472.44 157.48,476.38 ; J2.55@203.74,492.13 157.48,492.13 ; 157.48,476.38 157.48,492.13
VCC_5V_LAUNCH: J4.2
VIN5V: C73.1 C78.1 C82.1 C86.1 C179.1 C180.1 C181.1 D6.2 D16.2 D17.2 D18.2 D19.2 D20.2 L4.2 R80.1 R83.2 R93.1 R178.2 U7.4 U7.5 U7.15 U7.28 | length 3320.7
  TopLayer - S1 (.GTL) w9.84: R178.2@202.76,1592.52 v2@343.5,1592.52 ; 1761.84,350.84 1772.22,361.22 1772.22,392.05 1772.38,392.22 1772.38,416.75 1774.98,419.36 1775.45,419.36 1792.42,436.33 v1(1792.42,489) 1824.95,489 D16.2@1825.49,488.47 ; D19.2@1840.74,661.26 1805.67,626.2 1805.67,531.44 1825.1,512.01 D16.2@1825.1,489.53 1847.97,489.53 1851.91,485.59 1851.91,424.68 1867.61,408.97 D17.2@1911.61,408.97 ; D19.2@1841.47,661.6 D20.2@1897.7,661.6 ; D20.2@1898.27,663.28 1897.7,662.71 D20.2@1897.7,661.6 ; D20.2@1899.39,662.51 D20.2@1898.48,661.6 ; D20.2@1907.33,653.29 1899.02,661.6 D20.2@1898.48,661.6 ; D18.2@1907.91,476.71 1910.42,474.21 D17.2@1910.42,411.41 ; D20.2@1908.78,653.29 1909.04,653.03 D6.2@1909.04,588.17 ; D20.2@1897.7,661.6 D20.2@1898.48,661.6
  TopLayer - S1 (.GTL) w10: 1337.46,451.28 1374.28,414.46 1374.28,384.06 1407.22,351.13 1760.37,351.13
  TopLayer - S1 (.GTL) w11.81: v1(53.15,1311.02) 53.15,1270.67 R93.1@54.13,1269.68 ; 201.77,1389.76 245.08,1389.76 253.94,1380.91 U7.15@253.94,1366.14 U7.15@253.94,1359.25 ; R80.1@293.31,1036.42 293.31,1157.48 U7.28@293.31,1177.17 U7.28@293.31,1184.06
  TopLayer - S1 (.GTL) w15.75: R83.2@287.4,835.63 287.4,938.98 v2(353.35,1004.92) ; R83.2@295.28,832.68 549.83,832.68 627.86,754.65 627.86,522.01 698.58,451.28 1337.46,451.28
  BottomLayer - S8 (.GBL) w19.68: v2(272.15,1009.84) v2(289.86,1009.84) ; v2(345.47,1597.44) v2(345.47,1615.16) v2(363.19,1615.16) v2(363.19,1597.44) v2(345.47,1597.44) ; v2(531.5,1261.81) v2(531.5,1279.53) v2(549.21,1279.53) v2(549.21,1261.81) v2(531.5,1261.81)
  other v2: 161.42,1416.34 161.42,1434.06
pads on no net: FID1.1 FID2.1 FID3.1 FID4.1 FID5.1 FID6.1 H1.1 H2.1 J1.6 J2. J2.1 J2.3 J2.4 J2.5 J2.6 J2.7 J2.8 J2.10 J2.11 J2.12 J2.13 J2.14 J2.15 J2.16 J2.17 J2.18 J2.21 J2.22 J2.23 J2.24 J2.25 J2.26 J2.27 J2.28 J2.33 J2.35 J2.36 J2.37 J2.38 J2.39 J2.40 J2.42 J2.45 J2.46 J2.49 J2.53 J2.56 J2.57 J2.60 J3.2 J3.3 J3.6 J4.3 J4.10 J4.12 J4.14 J4.16 J4.18 J4.20 J5.8 J5.10 J5.15 J5.16 J5.17 J5.19 LBL1.0 Q1.0 Q2.0 Q3.0 Q4.0 Q5.0 Q6.0 T1.4 T1.5 T1.12 T1.13 T2.4 T2.5 T2.12 T2.13 U1.J1 U1.J9 U1.L1 U1.L9 U3.13 U3.15 U4.3@2263.09,698.82 U4.8@2295.96,698.82 U5.13 U5.15 U6.3@2263.09,1505.91 U6.8@2295.96,1505.91 U7.12 U11.A3 U11.A4 U11.A6 U11.A13 U11.B13 U11.C6 U11.F15 U11.F16 U11.F17 U11.G15 U11.G16 U11.G17 U11.G18 U11.L18 U11.M5 U11.M15 U11.M17 U11.M18 U11.N17 U11.N18 U11.P15 U11.P16 U11.P17 U11.P18 U11.R7 U11.R8 U11.R9 U11.R17 U11.R18 U11.T6 U11.T7 U11.T8 U11.T9 U11.T11 U11.T18 U11.U6 U11.U7 U11.U8 U11.U10 U11.V6 U11.V8 U11.V9 U13.1 U13.11 U14.1 U14.13 U14.16 U14.17 U15.1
